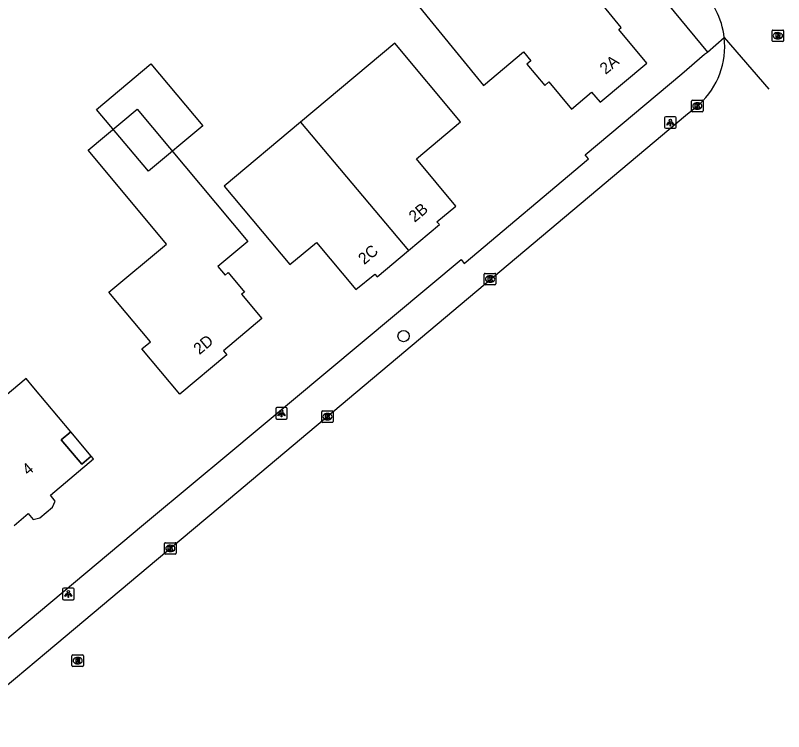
# Model space of a CAD drawing. Extents: x 156651 to 158072, y 387631 to 388990.
# Drawn here: x 157592.7 to 157659.5, y 387903.7 to 387966 of the extents above; entities that cross this region are included whole.
import ezdxf

# ---------------------------------------------------------------- set-up
doc = ezdxf.new("R2010")
doc.units = 0
for name, color, linetype in [('IMGEO_Boom', 7, 'Continuous'), ('IMGEO_Kolk', 7, 'Continuous'), ('IMGEO_Lichtpunt', 7, 'Continuous'), ('IMGEO_Pand', 7, 'Continuous'), ('IMGEO_Pand_nummerreeks', 7, 'Continuous'), ('IMGEO_Pand_overbouw', 7, 'Continuous'), ('IMGEO_Pand_vergunning_verleend', 7, 'Continuous'), ('IMGEO_Rijbaan_lokaal_open', 7, 'Continuous'), ('IMGEO_Rioolput', 7, 'Continuous'), ('IMGEO_Voetpad_open', 7, 'Continuous')]:
    doc.layers.add(name, color=color, linetype=linetype)

msp = doc.modelspace()

# ---------------------------------------------------------------- linework, layer by layer
at = {"layer": 'IMGEO_Boom'}
msp.add_circle((157626.477, 387938.126), 0.489, dxfattribs=at)
at = {"layer": 'IMGEO_Kolk'}
for p, q in [((157651.517, 387957.709), (157651.517, 387958.561)), ((157651.592, 387958.635), (157652.444, 387958.635)), ((157652.005, 387958.415), (157652.03, 387958.415)), ((157652.518, 387958.561), (157652.518, 387957.709)), ((157652.444, 387957.635), (157651.592, 387957.635)), ((157652.028, 387957.855), (157652.003, 387957.855)), ((157633.496, 387942.656), (157633.496, 387943.508)), ((157633.571, 387943.582), (157634.423, 387943.582)), ((157633.984, 387943.362), (157634.009, 387943.362)), ((157634.497, 387943.508), (157634.497, 387942.656)), ((157634.007, 387942.802), (157633.982, 387942.802)), ((157634.423, 387942.582), (157633.571, 387942.582)), ((157619.358, 387930.69), (157619.358, 387931.542)), ((157619.433, 387931.616), (157620.285, 387931.616)), ((157619.846, 387931.396), (157619.871, 387931.396)), ((157620.359, 387931.542), (157620.359, 387930.69)), ((157619.869, 387930.836), (157619.844, 387930.836)), ((157620.285, 387930.616), (157619.433, 387930.616)), ((157605.695, 387919.223), (157605.695, 387920.075)), ((157605.77, 387920.149), (157606.622, 387920.149)), ((157606.696, 387920.075), (157606.696, 387919.223)), ((157606.206, 387919.369), (157606.181, 387919.369)), ((157606.183, 387919.929), (157606.208, 387919.929)), ((157606.622, 387919.149), (157605.77, 387919.149))]:
    msp.add_line(p, q, dxfattribs=at)
for points in [[(157651.517, 387957.709), (157651.517, 387958.561)], [(157651.592, 387958.635), (157652.444, 387958.635)], [(157651.838, 387958.335), (157651.961, 387958.335), (157651.961, 387958.184), (157652.091, 387958.335), (157652.255, 387958.335), (157652.109, 387958.184), (157652.262, 387957.935), (157652.11, 387957.935), (157652.025, 387958.099), (157651.961, 387958.032), (157651.961, 387957.935), (157651.838, 387957.935), (157651.838, 387958.335)], [(157652.518, 387958.561), (157652.518, 387957.709)], [(157652.444, 387957.635), (157651.592, 387957.635)], [(157633.496, 387942.656), (157633.496, 387943.508)], [(157633.571, 387943.582), (157634.423, 387943.582)], [(157634.497, 387943.508), (157634.497, 387942.656)], [(157633.817, 387943.282), (157633.94, 387943.282), (157633.94, 387943.131), (157634.07, 387943.282), (157634.234, 387943.282), (157634.088, 387943.131), (157634.241, 387942.882), (157634.089, 387942.882), (157634.004, 387943.046), (157633.94, 387942.979), (157633.94, 387942.882), (157633.817, 387942.882), (157633.817, 387943.282)], [(157634.423, 387942.582), (157633.571, 387942.582)], [(157619.358, 387930.69), (157619.358, 387931.542)], [(157619.433, 387931.616), (157620.285, 387931.616)], [(157619.679, 387931.316), (157619.802, 387931.316), (157619.802, 387931.165), (157619.932, 387931.316), (157620.096, 387931.316), (157619.95, 387931.165), (157620.103, 387930.916), (157619.951, 387930.916), (157619.866, 387931.08), (157619.802, 387931.013), (157619.802, 387930.916), (157619.679, 387930.916), (157619.679, 387931.316)], [(157620.359, 387931.542), (157620.359, 387930.69)], [(157620.285, 387930.616), (157619.433, 387930.616)], [(157605.695, 387919.223), (157605.695, 387920.075)], [(157605.77, 387920.149), (157606.622, 387920.149)], [(157606.696, 387920.075), (157606.696, 387919.223)], [(157606.016, 387919.849), (157606.139, 387919.849), (157606.139, 387919.698), (157606.269, 387919.849), (157606.433, 387919.849), (157606.287, 387919.698), (157606.44, 387919.449), (157606.288, 387919.449), (157606.203, 387919.613), (157606.139, 387919.546), (157606.139, 387919.449), (157606.016, 387919.449), (157606.016, 387919.849)], [(157606.622, 387919.149), (157605.77, 387919.149)]]:
    msp.add_lwpolyline(points, dxfattribs=at)
for centre, start, end in [((157651.594, 387958.559), 91.55205, 178.44795), ((157651.594, 387958.559), 91.55205, 178.44795), ((157652.442, 387958.559), 1.55205, 88.44795), ((157652.442, 387958.559), 1.55205, 88.44795), ((157651.594, 387957.711), 181.55205, 268.44795), ((157651.594, 387957.711), 181.55205, 268.44795), ((157652.442, 387957.711), 271.55205, 358.44795), ((157652.442, 387957.711), 271.55205, 358.44795), ((157633.573, 387943.506), 91.55205, 178.44795), ((157633.573, 387943.506), 91.55205, 178.44795), ((157634.421, 387943.506), 1.55205, 88.44795), ((157634.421, 387943.506), 1.55205, 88.44795), ((157633.573, 387942.658), 181.55205, 268.44795), ((157633.573, 387942.658), 181.55205, 268.44795), ((157634.421, 387942.658), 271.55205, 358.44795), ((157634.421, 387942.658), 271.55205, 358.44795), ((157619.435, 387931.54), 91.55205, 178.44795), ((157619.435, 387931.54), 91.55205, 178.44795), ((157620.283, 387931.54), 1.55205, 88.44795), ((157620.283, 387931.54), 1.55205, 88.44795), ((157619.435, 387930.692), 181.55205, 268.44795), ((157619.435, 387930.692), 181.55205, 268.44795), ((157620.283, 387930.692), 271.55205, 358.44795), ((157620.283, 387930.692), 271.55205, 358.44795), ((157605.772, 387920.073), 91.55205, 178.44795), ((157605.772, 387920.073), 91.55205, 178.44795), ((157606.62, 387920.073), 1.55205, 88.44795), ((157606.62, 387920.073), 1.55205, 88.44795), ((157605.772, 387919.225), 181.55205, 268.44795), ((157605.772, 387919.225), 181.55205, 268.44795), ((157606.62, 387919.225), 271.55205, 358.44795), ((157606.62, 387919.225), 271.55205, 358.44795)]:
    msp.add_arc(centre, 0.0765, start, end, dxfattribs=at)
for centre, major_axis, ratio, start_param, end_param in [((157652.004, 387958.135), (-0.387, 0.002), 0.722429, 4.712389, 7.853982), ((157652.029, 387958.135), (-0.39, 0.002), 0.717154, 1.570796, 4.712389), ((157633.983, 387943.082), (-0.387, 0.002), 0.722429, 4.712389, 7.853982), ((157634.008, 387943.082), (-0.39, 0.002), 0.717154, 1.570796, 4.712389), ((157619.845, 387931.116), (-0.387, 0.002), 0.722429, 4.712389, 7.853982), ((157619.87, 387931.116), (-0.39, 0.002), 0.717154, 1.570796, 4.712389), ((157606.182, 387919.649), (-0.387, 0.002), 0.722429, 4.712389, 7.853982), ((157606.207, 387919.649), (-0.39, 0.002), 0.717154, 1.570796, 4.712389)]:
    msp.add_ellipse(centre, major_axis=major_axis, ratio=ratio, start_param=start_param, end_param=end_param, dxfattribs=at)
at = {"layer": 'IMGEO_Lichtpunt'}
for p, q in [((157649.175, 387957.103), (157649.175, 387956.296)), ((157649.175, 387957.103), (157649.175, 387956.296)), ((157650.077, 387957.198), (157649.269, 387957.198)), ((157650.077, 387957.198), (157649.269, 387957.198)), ((157650.171, 387956.296), (157650.171, 387957.103)), ((157650.171, 387956.296), (157650.171, 387957.103)), ((157649.269, 387956.202), (157650.077, 387956.202)), ((157649.269, 387956.202), (157650.077, 387956.202)), ((157615.364, 387931.804), (157615.364, 387930.997)), ((157615.364, 387931.804), (157615.364, 387930.997)), ((157616.266, 387931.899), (157615.458, 387931.899)), ((157616.266, 387931.899), (157615.458, 387931.899)), ((157616.36, 387930.997), (157616.36, 387931.804)), ((157616.36, 387930.997), (157616.36, 387931.804)), ((157615.458, 387930.903), (157616.266, 387930.903)), ((157615.458, 387930.903), (157616.266, 387930.903)), ((157596.829, 387916.092), (157596.829, 387915.285)), ((157596.829, 387916.092), (157596.829, 387915.285)), ((157597.731, 387916.187), (157596.923, 387916.187)), ((157597.731, 387916.187), (157596.923, 387916.187)), ((157597.825, 387915.285), (157597.825, 387916.092)), ((157597.825, 387915.285), (157597.825, 387916.092)), ((157596.923, 387915.191), (157597.731, 387915.191)), ((157596.923, 387915.191), (157597.731, 387915.191))]:
    msp.add_line(p, q, dxfattribs=at)
for points in [[(157649.549, 387956.767), (157649.588, 387956.739), (157649.4, 387956.477), (157649.362, 387956.504), (157649.549, 387956.767)], [(157649.651, 387956.719), (157649.698, 387956.719), (157649.698, 387956.397), (157649.651, 387956.397), (157649.651, 387956.719)], [(157649.761, 387956.739), (157649.799, 387956.766), (157649.986, 387956.504), (157649.947, 387956.476), (157649.761, 387956.739)], [(157615.738, 387931.468), (157615.777, 387931.44), (157615.589, 387931.178), (157615.551, 387931.205), (157615.738, 387931.468)], [(157615.84, 387931.42), (157615.887, 387931.42), (157615.887, 387931.098), (157615.84, 387931.098), (157615.84, 387931.42)], [(157615.95, 387931.44), (157615.988, 387931.467), (157616.175, 387931.205), (157616.136, 387931.177), (157615.95, 387931.44)], [(157597.203, 387915.756), (157597.242, 387915.728), (157597.054, 387915.466), (157597.016, 387915.493), (157597.203, 387915.756)], [(157597.305, 387915.708), (157597.352, 387915.708), (157597.352, 387915.386), (157597.305, 387915.386), (157597.305, 387915.708)], [(157597.415, 387915.728), (157597.453, 387915.755), (157597.64, 387915.493), (157597.601, 387915.465), (157597.415, 387915.728)]]:
    msp.add_lwpolyline(points, dxfattribs=at)
for centre in [(157649.674, 387956.901), (157615.863, 387931.602), (157597.328, 387915.89)]:
    msp.add_circle(centre, 0.0994, dxfattribs=at)
for centre, start, end in [((157649.269, 387957.103), 90, 180), ((157649.269, 387957.103), 90, 180), ((157650.077, 387957.103), 0, 90), ((157650.077, 387957.103), 0, 90), ((157649.269, 387956.296), 180, 270), ((157649.269, 387956.296), 180, 270), ((157650.077, 387956.296), 270, 0), ((157650.077, 387956.296), 270, 360), ((157615.458, 387931.804), 90, 180), ((157615.458, 387931.804), 90, 180), ((157616.266, 387931.804), 0, 90), ((157616.266, 387931.804), 0, 90), ((157615.458, 387930.997), 180, 270), ((157615.458, 387930.997), 180, 270), ((157616.266, 387930.997), 270, 0), ((157616.266, 387930.997), 270, 360), ((157596.923, 387916.092), 90, 180), ((157596.923, 387916.092), 90, 180), ((157597.731, 387916.092), 0, 90), ((157597.731, 387916.092), 0, 90), ((157596.923, 387915.285), 180, 270), ((157596.923, 387915.285), 180, 270), ((157597.731, 387915.285), 270, 0), ((157597.731, 387915.285), 270, 360)]:
    msp.add_arc(centre, 0.0946, start, end, dxfattribs=at)
at = {"layer": 'IMGEO_Pand'}
for points in [[(157641.855, 387971.008), (157641.001, 387970.283), (157639.782, 387971.718), (157635.327, 387967.986), (157633.419, 387970.249), (157631.727, 387968.846), (157630.652, 387970.127), (157627.336, 387967.407), (157633.43, 387959.935), (157636.9, 387962.84), (157637.544, 387962.071), (157637.193, 387961.773), (157638.755, 387959.934), (157639.092, 387960.23), (157641.072, 387957.862), (157642.829, 387959.338), (157643.558, 387958.481), (157647.631, 387961.869), (157645.199, 387964.783), (157645.409, 387964.97), (157643.558, 387967.211), (157644.417, 387967.948), (157641.855, 387971.008)], [(157626.893, 387945.555), (157629.586, 387947.818), (157629.371, 387948.061), (157631.026, 387949.435), (157627.593, 387953.535), (157631.434, 387956.755), (157625.707, 387963.598), (157617.505, 387956.73)], [(157599.042, 387954.289), (157603.308, 387957.854), (157612.93, 387946.343), (157610.336, 387944.191), (157610.966, 387943.431), (157611.23, 387943.65), (157612.653, 387941.958), (157612.384, 387941.756), (157614.155, 387939.661), (157610.81, 387936.833), (157611.096, 387936.492), (157607.024, 387933.079), (157603.727, 387937.018), (157604.455, 387937.628), (157600.851, 387941.944), (157605.871, 387946.12), (157605.749, 387946.265), (157599.042, 387954.289)], [(157617.505, 387956.73), (157610.862, 387951.168), (157616.594, 387944.337), (157618.902, 387946.258), (157622.329, 387942.166), (157623.968, 387943.52), (157624.18, 387943.276), (157626.893, 387945.555)], [(157617.505, 387956.73), (157626.893, 387945.555)], [(157592.618, 387921.646), (157593.845, 387922.697), (157594.275, 387922.157), (157594.833, 387922.306), (157595.947, 387923.253), (157596.187, 387923.766), (157595.767, 387924.281), (157599.518, 387927.436), (157599.318, 387927.679), (157598.487, 387926.991), (157596.715, 387929.107), (157597.543, 387929.8), (157594.333, 387933.634), (157593.657, 387934.44), (157589.6, 387931.051), (157585.942, 387935.417), (157585.723, 387935.231), (157584.558, 387936.622), (157582.477, 387936.868), (157581.108, 387935.677)]]:
    msp.add_lwpolyline(points, dxfattribs=at)
at = {"layer": 'IMGEO_Pand_overbouw'}
msp.add_lwpolyline([(157597.543, 387929.8), (157596.715, 387929.107), (157598.487, 387926.991), (157599.318, 387927.679)], close=True, dxfattribs=at)
at = {"layer": 'IMGEO_Pand_vergunning_verleend'}
msp.add_lwpolyline([(157604.493, 387961.802), (157609.008, 387956.413), (157604.286, 387952.457), (157599.771, 387957.845), (157604.493, 387961.802)], dxfattribs=at)
at = {"layer": 'IMGEO_Rijbaan_lokaal_open'}
for points in [[(157654.36, 387964.093), (157658.238, 387959.617)], [(157652.194, 387958.294), (157652.019, 387958.134), (157650.994, 387957.28), (157610.522, 387923.276), (157605.897, 387919.391), (157595.414, 387910.583), (157592.733, 387908.347), (157587.171, 387903.71)]]:
    msp.add_lwpolyline(points, dxfattribs=at)
for centre, radius, start, end in [((157647.546, 387963.337), 6.856, 6.32865, 48.27385), ((157647.54, 387963.336), 6.861, 312.70473, 6.33268)]:
    msp.add_arc(centre, radius, start, end, dxfattribs=at)
at = {"layer": 'IMGEO_Rioolput'}
for p, q in [((157658.596, 387964.75), (157659.448, 387964.75)), ((157658.521, 387963.824), (157658.521, 387964.676)), ((157659.009, 387964.53), (157659.034, 387964.53)), ((157659.522, 387964.676), (157659.522, 387963.824)), ((157659.448, 387963.75), (157658.596, 387963.75)), ((157659.032, 387963.97), (157659.007, 387963.97)), ((157597.639, 387909.464), (157597.639, 387910.316)), ((157597.714, 387910.39), (157598.566, 387910.39)), ((157598.127, 387910.17), (157598.152, 387910.17)), ((157598.64, 387910.316), (157598.64, 387909.464)), ((157598.566, 387909.39), (157597.714, 387909.39)), ((157598.15, 387909.61), (157598.125, 387909.61))]:
    msp.add_line(p, q, dxfattribs=at)
for points in [[(157658.596, 387964.75), (157659.448, 387964.75)], [(157658.521, 387963.824), (157658.521, 387964.676)], [(157659.11, 387964.448), (157658.858, 387964.45), (157658.858, 387964.05)], [(157658.858, 387964.05), (157658.982, 387964.05), (157658.982, 387964.212), (157658.993, 387964.212)], [(157659.036, 387964.369), (157658.982, 387964.369), (157658.982, 387964.288)], [(157658.982, 387964.288), (157659.034, 387964.288)], [(157659.04, 387964.183), (157659.111, 387964.05), (157659.251, 387964.05), (157659.186, 387964.176)], [(157659.522, 387964.676), (157659.522, 387963.824)], [(157659.448, 387963.75), (157658.596, 387963.75)], [(157597.639, 387909.464), (157597.639, 387910.316)], [(157597.714, 387910.39), (157598.566, 387910.39)], [(157598.228, 387910.088), (157597.976, 387910.09), (157597.976, 387909.69)], [(157598.154, 387910.009), (157598.1, 387910.009), (157598.1, 387909.928)], [(157598.1, 387909.928), (157598.152, 387909.928)], [(157598.64, 387910.316), (157598.64, 387909.464)], [(157598.566, 387909.39), (157597.714, 387909.39)], [(157597.976, 387909.69), (157598.1, 387909.69), (157598.1, 387909.852), (157598.111, 387909.852)], [(157598.158, 387909.823), (157598.229, 387909.69), (157598.369, 387909.69), (157598.304, 387909.816)]]:
    msp.add_lwpolyline(points, dxfattribs=at)
for centre, radius, start, end in [((157658.598, 387964.674), 0.0765, 91.55205, 178.44795), ((157658.598, 387964.674), 0.0765, 91.55205, 178.44795), ((157659.446, 387964.674), 0.0765, 1.55205, 88.44795), ((157659.446, 387964.674), 0.0765, 1.55205, 88.44795), ((157658.992, 387964.159), 0.0533, 26.02933, 88.69889), ((157659.018, 387964.477), 0.19, 274.7715, 282.96867), ((157659.042, 387964.273), 0.0964, 77.00612, 93.18647), ((157659.056, 387964.33), 0.0378, 276.66336, 79.67722), ((157659.109, 387964.338), 0.109, 350.36119, 89.41601), ((157659.107, 387964.338), 0.112, 277.58423, 350.98172), ((157659.091, 387964.123), 0.108, 29.51342, 73.79051), ((157658.598, 387963.826), 0.0765, 181.55205, 268.44795), ((157658.598, 387963.826), 0.0765, 181.55205, 268.44795), ((157659.446, 387963.826), 0.0765, 271.55205, 358.44795), ((157659.446, 387963.826), 0.0765, 271.55205, 358.44795), ((157597.716, 387910.314), 0.0765, 91.55205, 178.44795), ((157597.716, 387910.314), 0.0765, 91.55205, 178.44795), ((157598.136, 387910.117), 0.19, 274.7715, 282.96867), ((157598.16, 387909.913), 0.0964, 77.00612, 93.18647), ((157598.174, 387909.97), 0.0378, 276.66336, 79.67722), ((157598.227, 387909.978), 0.109, 350.36119, 89.41601), ((157598.225, 387909.978), 0.112, 277.58423, 350.98172), ((157598.564, 387910.314), 0.0765, 1.55205, 88.44795), ((157598.564, 387910.314), 0.0765, 1.55205, 88.44795), ((157597.716, 387909.466), 0.0765, 181.55205, 268.44795), ((157597.716, 387909.466), 0.0765, 181.55205, 268.44795), ((157598.11, 387909.799), 0.0533, 26.02933, 88.69889), ((157598.209, 387909.763), 0.108, 29.51342, 73.79051), ((157598.564, 387909.466), 0.0765, 271.55205, 358.44795), ((157598.564, 387909.466), 0.0765, 271.55205, 358.44795)]:
    msp.add_arc(centre, radius, start, end, dxfattribs=at)
for centre, major_axis, ratio, start_param, end_param in [((157659.008, 387964.25), (-0.387, 0.002), 0.722429, 4.712389, 7.853982), ((157659.033, 387964.25), (-0.39, 0.002), 0.717154, 1.570796, 4.712389), ((157598.126, 387909.89), (-0.387, 0.002), 0.722429, 4.712389, 7.853982), ((157598.151, 387909.89), (-0.39, 0.002), 0.717154, 1.570796, 4.712389)]:
    msp.add_ellipse(centre, major_axis=major_axis, ratio=ratio, start_param=start_param, end_param=end_param, dxfattribs=at)
at = {"layer": 'IMGEO_Voetpad_open'}
for points in [[(157635.307, 387982.52), (157636.218, 387983.074), (157652.9, 387962.822)], [(157652.9, 387962.822), (157654.36, 387964.093)], [(157585.134, 387906.15), (157590.77, 387910.755), (157603.872, 387921.744), (157608.52, 387925.626), (157610.764, 387927.467), (157611.111, 387927.751), (157631.486, 387944.793), (157631.753, 387944.442), (157642.563, 387953.548), (157642.274, 387953.88), (157650.669, 387960.94), (157652.642, 387962.641), (157652.9, 387962.822)]]:
    msp.add_lwpolyline(points, dxfattribs=at)

# ---------------------------------------------------------------- texts
at = {"layer": 'IMGEO_Pand_nummerreeks'}
for s, rotation, p in [('2A', 39.55701, (157644.041, 387960.838)), ('2B', 39.83776, (157627.438, 387947.976)), ('2C', 39.83776, (157623.05, 387944.29)), ('2D', 39.96954, (157608.721, 387936.457)), ('4', 39.99245, (157593.828, 387925.951))]:
    msp.add_text(s, height=1, rotation=rotation, dxfattribs=at).set_placement(p)

doc.saveas('drawing.dxf')
